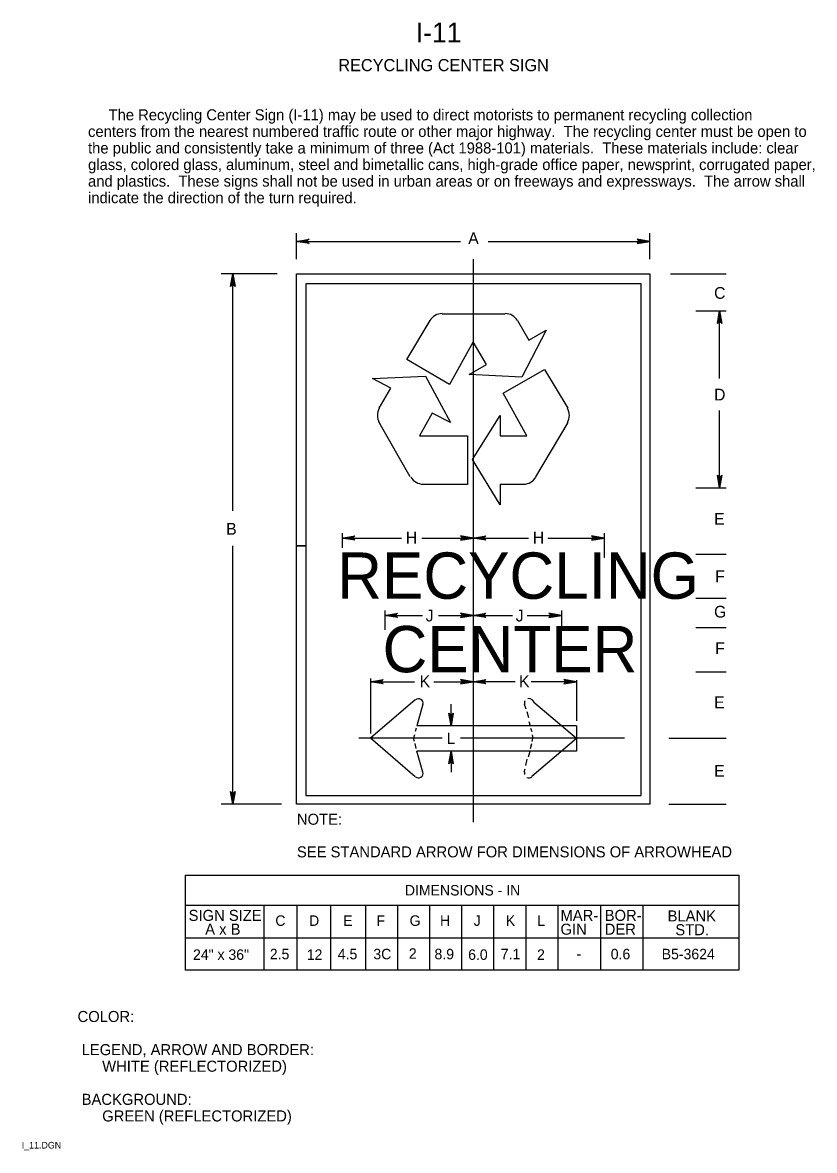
# Model space of a CAD drawing. Extents: x 0.013 to 0.192, y 0.004 to 0.259.
import ezdxf

# ---------------------------------------------------------------- set-up
doc = ezdxf.new("R2010")
doc.units = 0
doc.layers.add('1', color=7, linetype='Continuous')
doc.layers.add('3', color=7, linetype='Continuous')

msp = doc.modelspace()

# ---------------------------------------------------------------- linework, layer by layer
at = {"layer": '1'}
for p, q in [((0.074625, 0.205625), (0.074625, 0.2115)), ((0.074625, 0.209625), (0.11175, 0.209625)), ((0.11800000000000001, 0.209625), (0.154625, 0.209625)), ((0.154625, 0.205625), (0.154625, 0.2115)), ((0.114625, 0.205625), (0.114625, 0.07825)), ((0.07025, 0.20225), (0.057625, 0.20225)), ((0.06025, 0.148625), (0.06025, 0.20225)), ((0.074625, 0.14075000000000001), (0.074625, 0.20225)), ((0.074625, 0.20225), (0.154625, 0.20225)), ((0.154625, 0.20225), (0.154625, 0.08225)), ((0.15925, 0.20225), (0.171875, 0.20225)), ((0.152625, 0.2), (0.07675, 0.2)), ((0.07675, 0.2), (0.07675, 0.14075000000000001)), ((0.152625, 0.08425), (0.152625, 0.2)), ((0.099625, 0.182875), (0.104875, 0.19175)), ((0.107625, 0.19325), (0.121875, 0.19325)), ((0.124625, 0.19175), (0.12725, 0.18725)), ((0.165, 0.193875), (0.171875, 0.193875)), ((0.170375, 0.178625), (0.170375, 0.193875)), ((0.131125, 0.1895), (0.12562500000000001, 0.178875)), ((0.12725, 0.18725), (0.131125, 0.1895)), ((0.114625, 0.186875), (0.10925, 0.17725)), ((0.11762500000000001, 0.18175), (0.114625, 0.186875)), ((0.10925, 0.17725), (0.099625, 0.182875)), ((0.11375, 0.1795), (0.11762500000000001, 0.18175)), ((0.091875, 0.178625), (0.10387500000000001, 0.179125)), ((0.10387500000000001, 0.179125), (0.1095, 0.168625)), ((0.12562500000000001, 0.178875), (0.11375, 0.1795)), ((0.121375, 0.17525000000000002), (0.13075, 0.180625)), ((0.13075, 0.180625), (0.136, 0.171875)), ((0.096, 0.176375), (0.091875, 0.178625)), ((0.093375, 0.171875), (0.096, 0.176375)), ((0.12675, 0.165625), (0.121375, 0.17525000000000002)), ((0.170375, 0.153875), (0.170375, 0.171375)), ((0.100375, 0.15637500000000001), (0.093375, 0.168625)), ((0.105375, 0.17075), (0.10250000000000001, 0.165625)), ((0.1095, 0.168625), (0.105375, 0.17075)), ((0.1145, 0.16025), (0.12075, 0.17025)), ((0.12075, 0.17025), (0.12075, 0.165625)), ((0.136, 0.168625), (0.12875, 0.15637500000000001)), ((0.10250000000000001, 0.165625), (0.113375, 0.165625)), ((0.113375, 0.165625), (0.113375, 0.154625)), ((0.12075, 0.165625), (0.12675, 0.165625)), ((0.12075, 0.15), (0.1145, 0.16025)), ((0.113375, 0.154625), (0.10312500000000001, 0.154625)), ((0.126, 0.154625), (0.12075, 0.154625)), ((0.12075, 0.154625), (0.12075, 0.15)), ((0.165, 0.153875), (0.171875, 0.153875)), ((0.085, 0.143625), (0.085, 0.14025)), ((0.14425, 0.143625), (0.14425, 0.138)), ((0.06025, 0.08225), (0.06025, 0.14075000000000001)), ((0.074625, 0.14075000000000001), (0.07675, 0.14075000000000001)), ((0.07675, 0.14075000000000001), (0.074625, 0.14075000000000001)), ((0.074625, 0.08225), (0.074625, 0.14075000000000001)), ((0.07675, 0.14075000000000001), (0.07675, 0.08425)), ((0.085, 0.14250000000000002), (0.098375, 0.14250000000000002)), ((0.10300000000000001, 0.14250000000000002), (0.114625, 0.14250000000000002)), ((0.114625, 0.14250000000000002), (0.12712500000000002, 0.14250000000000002)), ((0.1315, 0.14250000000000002), (0.14425, 0.14250000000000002)), ((0.165, 0.138875), (0.171875, 0.138875)), ((0.165, 0.128875), (0.171875, 0.128875)), ((0.094625, 0.12612500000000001), (0.094625, 0.12175)), ((0.134625, 0.12612500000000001), (0.134625, 0.12175)), ((0.094625, 0.125), (0.10312500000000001, 0.125)), ((0.10675, 0.125), (0.114625, 0.125)), ((0.114625, 0.125), (0.1235, 0.125)), ((0.12687500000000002, 0.125), (0.134625, 0.125)), ((0.165, 0.12225), (0.171875, 0.12225)), ((0.091375, 0.11075), (0.091375, 0.09825)), ((0.091375, 0.11), (0.101375, 0.11)), ((0.10575, 0.11), (0.114625, 0.11)), ((0.124125, 0.11), (0.114625, 0.11)), ((0.138, 0.11), (0.12775, 0.11)), ((0.138, 0.110375), (0.138, 0.101125)), ((0.165, 0.11225), (0.171875, 0.11225)), ((0.1015, 0.105875), (0.091375, 0.09725)), ((0.10325000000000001, 0.104875), (0.10187500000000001, 0.1)), ((0.109625, 0.1), (0.109625, 0.104875)), ((0.12612500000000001, 0.104875), (0.1265, 0.10387500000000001)), ((0.12787500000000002, 0.106), (0.128375, 0.105375)), ((0.128375, 0.105375), (0.138, 0.09725)), ((0.12675, 0.10325000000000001), (0.12712500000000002, 0.10187500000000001)), ((0.138, 0.1), (0.10187500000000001, 0.1)), ((0.12725, 0.101), (0.1275, 0.1)), ((0.138, 0.1), (0.138, 0.09425)), ((0.107625, 0.09725), (0.08875, 0.09725)), ((0.1015, 0.0885), (0.091375, 0.09725)), ((0.101375, 0.098), (0.101125, 0.09725)), ((0.101375, 0.0965), (0.101125, 0.09725)), ((0.10175000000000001, 0.0995), (0.1015, 0.09875)), ((0.148875, 0.09725), (0.11175, 0.09725)), ((0.12762500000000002, 0.0995), (0.12787500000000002, 0.09875)), ((0.12787500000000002, 0.088625), (0.138, 0.09725)), ((0.128, 0.098), (0.128125, 0.09725)), ((0.128, 0.0965), (0.128125, 0.09725)), ((0.15887500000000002, 0.09725), (0.171875, 0.09725)), ((0.10175000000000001, 0.094875), (0.1015, 0.096)), ((0.12762500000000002, 0.094875), (0.12787500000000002, 0.096)), ((0.10325000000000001, 0.0895), (0.10187500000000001, 0.09425)), ((0.138, 0.09425), (0.10187500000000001, 0.09425)), ((0.109625, 0.09425), (0.109625, 0.0895)), ((0.1265, 0.091), (0.12687500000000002, 0.0925)), ((0.12712500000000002, 0.093), (0.1275, 0.09425)), ((0.12612500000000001, 0.0895), (0.12637500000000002, 0.09025)), ((0.07675, 0.08425), (0.152625, 0.08425)), ((0.07125000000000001, 0.08225), (0.057625, 0.08225)), ((0.154625, 0.08225), (0.074625, 0.08225)), ((0.15887500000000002, 0.08225), (0.171875, 0.08225))]:
    msp.add_line(p, q, dxfattribs=at)
for points in [[(0.07725, 0.209375), (0.077125, 0.2095), (0.074625, 0.209625), (0.07725, 0.209375), (0.0775, 0.209125), (0.074625, 0.209625), (0.077125, 0.20975), (0.07725, 0.209875), (0.074625, 0.209625), (0.0775, 0.210125), (0.07725, 0.209875)], [(0.152, 0.209375), (0.152125, 0.2095), (0.154625, 0.209625), (0.152, 0.209375), (0.15175, 0.209125), (0.154625, 0.209625), (0.152125, 0.20975), (0.152, 0.209875), (0.154625, 0.209625), (0.15175, 0.210125), (0.152, 0.209875)], [(0.06, 0.199625), (0.060125, 0.19975), (0.06025, 0.20225), (0.06, 0.199625), (0.059750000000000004, 0.199375), (0.06025, 0.20225), (0.060375, 0.19975), (0.0605, 0.199625), (0.06025, 0.20225), (0.06075, 0.199375), (0.0605, 0.199625)], [(0.170125, 0.19125), (0.17025, 0.19137500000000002), (0.170375, 0.193875), (0.170125, 0.19125), (0.169875, 0.191), (0.170375, 0.193875), (0.1705, 0.19137500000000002), (0.170625, 0.19125), (0.170375, 0.193875), (0.170875, 0.191), (0.170625, 0.19125)], [(0.170625, 0.1565), (0.1705, 0.15637500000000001), (0.170375, 0.153875), (0.170625, 0.1565), (0.170875, 0.15675), (0.170375, 0.153875), (0.17025, 0.15637500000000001), (0.170125, 0.1565), (0.170375, 0.153875), (0.169875, 0.15675), (0.170125, 0.1565)], [(0.08762500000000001, 0.14225000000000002), (0.08750000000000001, 0.142375), (0.085, 0.14250000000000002), (0.08762500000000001, 0.14225000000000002), (0.08787500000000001, 0.14200000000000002), (0.085, 0.14250000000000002), (0.08750000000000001, 0.142625), (0.08762500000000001, 0.14275000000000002), (0.085, 0.14250000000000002), (0.08787500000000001, 0.14300000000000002), (0.08762500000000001, 0.14275000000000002)], [(0.112, 0.14225000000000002), (0.112125, 0.142375), (0.114625, 0.14250000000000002), (0.112, 0.14225000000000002), (0.11175, 0.14200000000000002), (0.114625, 0.14250000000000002), (0.112125, 0.142625), (0.112, 0.14275000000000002), (0.114625, 0.14250000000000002), (0.11175, 0.14300000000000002), (0.112, 0.14275000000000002)], [(0.11725000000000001, 0.14225000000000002), (0.117125, 0.142375), (0.114625, 0.14250000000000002), (0.11725000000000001, 0.14225000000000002), (0.11750000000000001, 0.14200000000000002), (0.114625, 0.14250000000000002), (0.117125, 0.142625), (0.11725000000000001, 0.14275000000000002), (0.114625, 0.14250000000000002), (0.11750000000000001, 0.14300000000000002), (0.11725000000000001, 0.14275000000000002)], [(0.141625, 0.14225000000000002), (0.14175000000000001, 0.142375), (0.14425, 0.14250000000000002), (0.141625, 0.14225000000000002), (0.141375, 0.14200000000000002), (0.14425, 0.14250000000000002), (0.14175000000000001, 0.142625), (0.141625, 0.14275000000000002), (0.14425, 0.14250000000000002), (0.141375, 0.14300000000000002), (0.141625, 0.14275000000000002)], [(0.09725, 0.12475), (0.097125, 0.124875), (0.094625, 0.125), (0.09725, 0.12475), (0.0975, 0.1245), (0.094625, 0.125), (0.097125, 0.12512500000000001), (0.09725, 0.12525), (0.094625, 0.125), (0.0975, 0.1255), (0.09725, 0.12525)], [(0.112, 0.12475), (0.112125, 0.124875), (0.114625, 0.125), (0.112, 0.12475), (0.11175, 0.1245), (0.114625, 0.125), (0.112125, 0.12512500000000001), (0.112, 0.12525), (0.114625, 0.125), (0.11175, 0.1255), (0.112, 0.12525)], [(0.11725000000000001, 0.12475), (0.117125, 0.124875), (0.114625, 0.125), (0.11725000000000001, 0.12475), (0.11750000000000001, 0.1245), (0.114625, 0.125), (0.117125, 0.12512500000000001), (0.11725000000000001, 0.12525), (0.114625, 0.125), (0.11750000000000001, 0.1255), (0.11725000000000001, 0.12525)], [(0.132, 0.12475), (0.132125, 0.124875), (0.134625, 0.125), (0.132, 0.12475), (0.13175, 0.1245), (0.134625, 0.125), (0.132125, 0.12512500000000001), (0.132, 0.12525), (0.134625, 0.125), (0.13175, 0.1255), (0.132, 0.12525)], [(0.094, 0.10975), (0.093875, 0.109875), (0.091375, 0.11), (0.094, 0.10975), (0.09425, 0.1095), (0.091375, 0.11), (0.093875, 0.110125), (0.094, 0.11025), (0.091375, 0.11), (0.09425, 0.1105), (0.094, 0.11025)], [(0.112, 0.10975), (0.112125, 0.109875), (0.114625, 0.11), (0.112, 0.10975), (0.11175, 0.1095), (0.114625, 0.11), (0.112125, 0.110125), (0.112, 0.11025), (0.114625, 0.11), (0.11175, 0.1105), (0.112, 0.11025)], [(0.11725000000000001, 0.10975), (0.117125, 0.109875), (0.114625, 0.11), (0.11725000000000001, 0.10975), (0.11750000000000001, 0.1095), (0.114625, 0.11), (0.117125, 0.110125), (0.11725000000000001, 0.11025), (0.114625, 0.11), (0.11750000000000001, 0.1105), (0.11725000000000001, 0.11025)], [(0.135375, 0.10975), (0.1355, 0.109875), (0.138, 0.11), (0.135375, 0.10975), (0.135125, 0.1095), (0.138, 0.11), (0.1355, 0.110125), (0.135375, 0.11025), (0.138, 0.11), (0.135125, 0.1105), (0.135375, 0.11025)], [(0.109875, 0.10262500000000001), (0.10975, 0.10250000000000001), (0.109625, 0.1), (0.109875, 0.10262500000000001), (0.110125, 0.10287500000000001), (0.109625, 0.1), (0.1095, 0.10250000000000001), (0.109375, 0.10262500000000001), (0.109625, 0.1), (0.109125, 0.10287500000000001), (0.109375, 0.10262500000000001)], [(0.109375, 0.091625), (0.1095, 0.09175), (0.109625, 0.09425), (0.109375, 0.091625), (0.109125, 0.091375), (0.109625, 0.09425), (0.10975, 0.09175), (0.109875, 0.091625), (0.109625, 0.09425), (0.110125, 0.091375), (0.109875, 0.091625)], [(0.0605, 0.084875), (0.060375, 0.08475), (0.06025, 0.08225), (0.0605, 0.084875), (0.06075, 0.085125), (0.06025, 0.08225), (0.060125, 0.08475), (0.06, 0.084875), (0.06025, 0.08225), (0.059750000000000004, 0.085125), (0.06, 0.084875)]]:
    msp.add_lwpolyline(points, dxfattribs=at)
for centre, radius, start, end in [((0.10760964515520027, 0.19007758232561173), 0.0032039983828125, 90.00000000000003, 149.9988666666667), ((0.12187923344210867, 0.19007758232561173), 0.0032039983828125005, 29.998961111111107, 90), ((0.09616426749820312, 0.17025259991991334), 0.0032039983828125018, 149.99896111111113, 210.00000000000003), ((0.1331754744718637, 0.1702510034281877), 0.0032039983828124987, 330, 29.99886666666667), ((0.10329906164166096, 0.15789477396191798), 0.0032039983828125, 210.00000000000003, 269.9988666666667), ((0.12604068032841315, 0.15789317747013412), 0.0032039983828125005, 269.99896111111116, 330.00000000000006), ((0.1022442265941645, 0.10511516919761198), 0.0010416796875, 345.0676583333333, 130.6957638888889), ((0.12724453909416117, 0.10511516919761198), 0.0010416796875, 149.73224722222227, 194.93234166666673), ((0.12724453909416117, 0.10511516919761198), 0.0010416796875, 49.304236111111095, 102.74835555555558), ((0.1022442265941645, 0.08928163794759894), 0.0010416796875, 229.30423611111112, 14.93234166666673), ((0.12724453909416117, 0.08928163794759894), 0.0010416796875, 165.06765833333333, 197.2154361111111), ((0.12724453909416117, 0.08928163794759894), 0.0010416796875, 243.42871388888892, 310.6957638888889)]:
    msp.add_arc(centre, radius, start, end, dxfattribs=at)
at = {"layer": '3'}
for p, q in [((0.0495, 0.06625), (0.17475000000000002, 0.06625)), ((0.0495, 0.06625), (0.0495, 0.04475)), ((0.17475000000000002, 0.06625), (0.17475000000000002, 0.04475)), ((0.17475000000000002, 0.059375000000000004), (0.0495, 0.059375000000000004)), ((0.06729158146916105, 0.059372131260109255), (0.06729158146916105, 0.044747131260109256)), ((0.07475, 0.059375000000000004), (0.07475, 0.04475)), ((0.082375, 0.059375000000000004), (0.082375, 0.04475)), ((0.09025, 0.059375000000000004), (0.09025, 0.04475)), ((0.0975, 0.059375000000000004), (0.0975, 0.04475)), ((0.10475, 0.059375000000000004), (0.10475, 0.04475)), ((0.112, 0.059375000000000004), (0.112, 0.04475)), ((0.11925000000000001, 0.059375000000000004), (0.11925000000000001, 0.04475)), ((0.1265, 0.059375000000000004), (0.1265, 0.04475)), ((0.13379158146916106, 0.059372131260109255), (0.13379158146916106, 0.044747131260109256)), ((0.14341658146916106, 0.059372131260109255), (0.14341658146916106, 0.044747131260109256)), ((0.15304158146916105, 0.059372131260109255), (0.15304158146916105, 0.044747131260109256)), ((0.17475000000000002, 0.052000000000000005), (0.0495, 0.052000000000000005)), ((0.17475000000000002, 0.04475), (0.0495, 0.04475))]:
    msp.add_line(p, q, dxfattribs=at)

# ---------------------------------------------------------------- texts
at = {"layer": '1'}
for s, height, p in [('I-11', 0.0045000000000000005, (0.10162500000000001, 0.254625)), ('RECYCLING CENTER SIGN', 0.00275025, (0.084125, 0.248125)), ('A', 0.0026632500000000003, (0.1135, 0.209)), ('C', 0.0026632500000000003, (0.169125, 0.196625)), ('D', 0.0026632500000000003, (0.169125, 0.173625)), ('E', 0.0026632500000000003, (0.169125, 0.1455)), ('B', 0.0026632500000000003, (0.058750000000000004, 0.14325000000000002)), ('H', 0.0026632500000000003, (0.099375, 0.14125000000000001)), ('H', 0.0026632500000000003, (0.128125, 0.14125000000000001)), ('RECYCLING', 0.010485, (0.083875, 0.12875)), ('F', 0.0026632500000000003, (0.169375, 0.1325)), ('J', 0.0026632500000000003, (0.10387500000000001, 0.123625)), ('J', 0.0026632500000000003, (0.12425, 0.123625)), ('G', 0.0026632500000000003, (0.169125, 0.1245)), ('CENTER', 0.010485, (0.094125, 0.112125)), ('F', 0.0026632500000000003, (0.169375, 0.11625)), ('K', 0.0026632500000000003, (0.10250000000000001, 0.10875)), ('K', 0.0026632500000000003, (0.125, 0.10875)), ('E', 0.0026632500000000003, (0.169125, 0.10400000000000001)), ('L', 0.002625, (0.108625, 0.095875)), ('E', 0.0026632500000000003, (0.169125, 0.0885)), ('NOTE:', 0.0024997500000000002, (0.07475, 0.077625)), ('SEE STANDARD ARROW FOR DIMENSIONS OF ARROWHEAD', 0.0024997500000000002, (0.07475, 0.07025)), ('COLOR:', 0.0024997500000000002, (0.025125, 0.033)), (' LEGEND, ARROW AND BORDER:', 0.0024997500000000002, (0.025125, 0.025500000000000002)), ('      WHITE (REFLECTORIZED)', 0.0024997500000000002, (0.025125, 0.021750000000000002)), (' BACKGROUND:', 0.0024997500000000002, (0.025125, 0.01425)), ('      GREEN (REFLECTORIZED)', 0.0024997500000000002, (0.025125, 0.0105)), ('I_11.DGN', 0.0015, (0.0125, 0.004375))]:
    msp.add_text(s, height=height, dxfattribs=at).set_placement(p)
at = {"layer": '3'}
for s, height, p in [('     The Recycling Center Sign (I-11) may be used to direct motorists to permanent recycling collection', 0.0024997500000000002, (0.0275, 0.23699950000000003)), ('centers from the nearest numbered traffic route or other major highway.  The recycling center must be open to', 0.0024997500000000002, (0.0275, 0.23324975)), ('the public and consistently take a minimum of three (Act 1988-101) materials.  These materials include: clear', 0.0024997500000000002, (0.0275, 0.2295)), ('glass, colored glass, aluminum, steel and bimetallic cans, high-grade office paper, newsprint, corrugated paper,', 0.0024997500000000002, (0.0275, 0.22575024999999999)), ('and plastics.  These signs shall not be used in urban areas or on freeways and expressways.  The arrow shall', 0.0024997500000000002, (0.0275, 0.2220005)), ('indicate the direction of the turn required. ', 0.0024997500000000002, (0.0275, 0.21825075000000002)), ('DIMENSIONS - IN', 0.0023752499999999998, (0.09916729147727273, 0.061625)), ('SIGN SIZE', 0.0024997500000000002, (0.05025, 0.055875)), ('C', 0.0023752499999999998, (0.069875, 0.05475)), ('D', 0.0023752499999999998, (0.0775, 0.05475)), ('E', 0.0023752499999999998, (0.08525, 0.05475)), ('F', 0.0023752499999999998, (0.09275, 0.05475)), ('G', 0.0023752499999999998, (0.10025, 0.05475)), ('H', 0.0023752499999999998, (0.107125, 0.05475)), ('J', 0.0023752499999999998, (0.11475, 0.05475)), ('K', 0.0023752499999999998, (0.122, 0.05475)), ('L', 0.0023752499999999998, (0.129125, 0.05475)), ('MAR-', 0.0024997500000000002, (0.134375, 0.055875)), ('BOR-', 0.0024997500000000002, (0.144375, 0.055875)), ('BLANK', 0.0024997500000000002, (0.15860372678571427, 0.05575)), ('A x B', 0.0024997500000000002, (0.054, 0.05275)), ('GIN', 0.0024997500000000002, (0.134375, 0.05275)), ('DER', 0.0024997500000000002, (0.144375, 0.05275)), ('STD.', 0.0024997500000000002, (0.16035372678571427, 0.052625)), ('24" x 36"', 0.0023752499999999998, (0.051245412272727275, 0.047062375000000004)), ('2.5', 0.0023752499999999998, (0.0686213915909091, 0.047187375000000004)), ('12', 0.0023752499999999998, (0.07697876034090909, 0.047062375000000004)), ('4.5', 0.0023752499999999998, (0.0839963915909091, 0.047187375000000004)), ('3C', 0.0023752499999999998, (0.09203957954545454, 0.047187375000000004)), ('2', 0.0023752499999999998, (0.10007353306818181, 0.047312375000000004)), ('8.9', 0.0023752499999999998, (0.10587211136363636, 0.047187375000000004)), ('6.0', 0.0023752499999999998, (0.11348847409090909, 0.047062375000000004)), ('7.1', 0.0023752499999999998, (0.12086539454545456, 0.047187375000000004)), ('2', 0.0023752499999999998, (0.12907353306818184, 0.047062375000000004)), ('0.6', 0.0023752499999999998, (0.1457435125, 0.047187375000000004)), ('B5-3624', 0.0023752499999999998, (0.15727095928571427, 0.047187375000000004)), ('-', 0.0023752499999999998, (0.138, 0.04725))]:
    msp.add_text(s, height=height, dxfattribs=at).set_placement(p)

doc.saveas('drawing.dxf')
